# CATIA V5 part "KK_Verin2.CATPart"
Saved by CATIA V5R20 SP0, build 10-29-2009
Part number: Verin2
Publications: "Esquisse.1"
Bounding box of the stored display mesh (mm): x 25.707 to 54.701, y 65.691 to 91.769, z -5 to 66.427
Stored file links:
  G:\Khaled_CFAO_2011\ST2M\ST2M_GR1\msallin\Khaled\Version_Finale\KK_Verin2.CATPart
  C:\Users\Mathieu\Desktop\Think Motion\JOUG-MELEE2.CATProduct
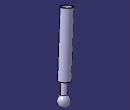
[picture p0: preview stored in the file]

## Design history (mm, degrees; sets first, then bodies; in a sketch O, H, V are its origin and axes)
External parameters (linked from other documents)
  `External.Taille du joug` = 100 mm
Set1
  Line1: linked copy from another document
  Line2: linked copy from another document
  Point1: linked copy from another document
Set2
  Plane1: type 2Lines, Element1 Line1, Element2 Line2
  Plane2: type 2Lines, Element1 Line1, Element2 Line2
  Plane3: type 2Lines, Element1 Sketch1.L1, Element2 Sketch1.L5
  Point2: type Center, Curve Sketch1
  DatumSurface1
Body1 (main body)
  Sketch1 on Plane1, origin (-0.277, 81.5078, 20.3771), H (1, 0.0034, 0), V (0.0008, -0.2425, 0.9701)
    line L1 (35.5541, 46.9883) -> (50.8247, -5.8493)
    point P1 (35.5541, 46.9883)
    point P2 (50.8247, -5.8493)
    line L2 (50.8247, -5.8493) -> (48.423, -6.5434)
    point P3 (48.423, -6.5434)
    line L3 (48.423, -6.5434) -> (51.1995, -16.1502)
    arc A1 centre (50, -21.0042) radius 5 from (51.3882, -25.8076) to (51.1995, -16.1502) ccw
    point P5 (50, -21.0042)
    point P6 (51.3882, -25.8076)
    reference projected line E1 (20.2094, 82.0734) -> (50, -21.0042) from Line1
    reference projected line E2 (20.2094, 82.0734) -> (50, -21.0042) from Line1
    reference projected line E3 (20.2094, 82.0734) -> (50, -21.0042) from Line1
    reference projected point E4 (50, -21.0042) from Point1
    reference projected point E5 (50, -21.0042) from Point1
    line L4 (35.5541, 46.9883) -> (34.7535, 46.7569)
    line L5 (34.7535, 46.7569) -> (46.97, 4.4869)
    point P8 (46.97, 4.4869)
    line L6 (46.97, 4.4869) -> (42.9671, 3.33)
    point P9 (42.9671, 3.33)
    reference projected line E6 (20.2094, 82.0734) -> (50, -21.0042) from Line1
    reference projected line E7 (20.2094, 82.0734) -> (50, -21.0042) from Line1
    distance P1 E1 = 5 {= `External.Taille du joug` /20}
    distance P2 E2 = 5 {= Sketch1.distance(P1 E1)}
    distance P3 E3 = 2.5 {= Sketch1.distance(P2 E2) /2}
    length L1 = 55 {= `External.Taille du joug` *(7/10-1/10-1/20)}
    length L3 = 10 {= `External.Taille du joug` /10}
    radius A1 = 5 {= `External.Taille du joug` /20}
    distance P5 E4 = 0
    distance P6 E5 = 5 {= Sketch1.radius(A1)}
    distance P9 E6 = 0
    length L4 = 0.8333 {= `External.Taille du joug`* (1/20-1/24)}
    length L5 = 44 {= Sketch1.length(L1) *4/5}
    distance P8 L1 = 0.8333 {= Sketch1.length(L4)}
    distance P6 E7 = 0
    perpendicularity: L2 L1
    parallelism: L3 L1, L5 L3, L6 L2
  Shaft1: profile Sketch1, axis Line1, angle 360
  Sketch2 on Plane1, origin (-0.277, 81.5078, 20.3771), H (1, 0.0034, 0), V (0.0008, -0.2425, 0.9701)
